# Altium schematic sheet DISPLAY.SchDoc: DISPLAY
size A4; CompanyName: Arduino srl; DrawnBy: Silvio Navaretti; DocumentNumber: ASX00039; SheetNumber: 4; SheetTotal: 8; RevAuthor: Silvio Navaretti
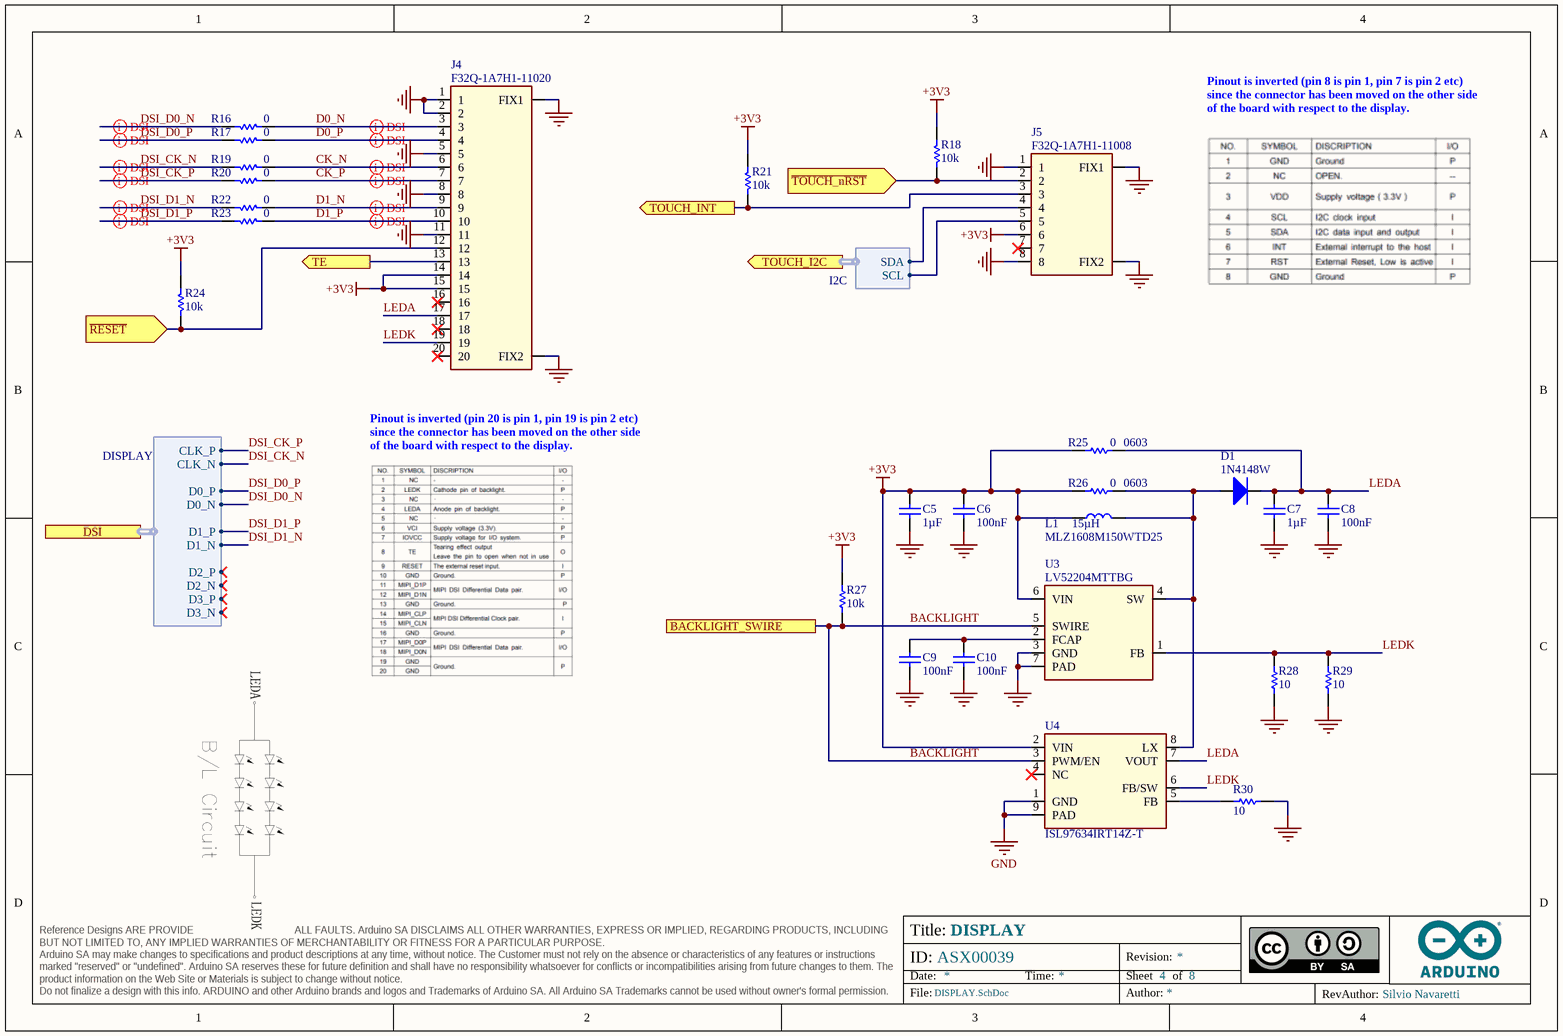
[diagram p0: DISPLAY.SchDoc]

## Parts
C5  value 1µF  [CAP-0603]  (hidden comment: TMK107BJ105MAHT)
C6  value 100nF  [CAP-0603]  (hidden comment: C0603C104K5RAC3190)
C7  value 1µF  [CAP-0603]  (hidden comment: TMK107BJ105MAHT)
C8  value 100nF  [CAP-0603]  (hidden comment: C0603C104K5RAC3190)
C9  value 100nF  [CAP-0603]  (hidden comment: C0603C104K5RAC3190)
C10  value 100nF  [CAP-0603]  (hidden comment: C0603C104K5RAC3190)
D1  1N4148W  [SOD123-1]
J4  F32Q-1A7H1-11020  [F32R-1A7H1-11020]
J5  F32Q-1A7H1-11008  [F32R-1A7H1-11008]
L1  MLZ1608M150WTD25  Inductance: 15µH  [L-0603]
R16  value 0  [RES-0603]  (hidden comment: CRCW06030000Z0EAC)
R17  value 0  [RES-0603]  (hidden comment: CRCW06030000Z0EAC)
R18  value 10k  [RES-0603]  (hidden comment: CRCW060310K0JNEAC)
R19  value 0  [RES-0603]  (hidden comment: CRCW06030000Z0EAC)
R20  value 0  [RES-0603]  (hidden comment: CRCW06030000Z0EAC)
R21  value 10k  [RES-0603]  (hidden comment: CRCW060310K0JNEAC)
R22  value 0  [RES-0603]  (hidden comment: CRCW06030000Z0EAC)
R23  value 0  [RES-0603]  (hidden comment: CRCW06030000Z0EAC)
R24  value 10k  [RES-0603]  (hidden comment: CRCW060310K0JNEAC)
R25  value 0  Case Code (Imperial): 0603  [RES-0603]  (hidden comment: CRCW06030000Z0EAC)
R26  value 0  Case Code (Imperial): 0603  [RES-0603]  (hidden comment: CRCW06030000Z0EAC)
R27  value 10k  [RES-0603]  (hidden comment: CRCW060310K0JNEAC)
R28  value 10  [RES-0603]  (hidden comment: CRCW060310R0FKEAC)
R29  value 10  [RES-0603]  (hidden comment: CRCW060310R0FKEAC)
R30  value 10  [RES-0603]  (hidden comment: CRCW060310R0FKEAC)
U3  LV52204MTTBG  [QFN65P200X200X80_HS-7L]
U4  ISL97634IRT14Z-T  [PQFN0P300X200X80_HS-9L]

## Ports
BACKLIGHT_SWIRE, DSI (harness DISPLAY), TE (out), TOUCH_I2C (out, harness I2C), TOUCH_INT (out), ~{RESET} (in), ~{TOUCH_nRST} (in)

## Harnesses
DISPLAY: CLK_N, CLK_P, D0_N, D0_P, D1_N, D1_P, D2_N, D2_P, D3_N, D3_P
I2C: SDA, SCL

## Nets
+3V3: C5.2 C6.2 J4.14 J4.15 J5.6 L1.1 R18.2 R21.2 R24.2 R25.1 R26.1 R27.2 U3.6(VIN) U4.2(VIN)
GND: C5.1 C6.1 C7.1 C8.1 C9.1 C10.1 J4.1 J4.2 J4.5 J4.8 J4.11 J4.FIX1 J4.FIX2 J5.1 J5.8 J5.FIX1 J5.FIX2 R28.1 R29.1 R30.1 U3.3(GND) U3.7(PAD) U4.1(GND) U4.9(PAD)
BACKLIGHT: R27.1 U3.5(SWIRE) U4.3(PWM/EN) ; port BACKLIGHT_SWIRE
CK_N: J4.6 R19.2
CK_P: J4.7 R20.2
D0_N: J4.3 R16.2
D0_P: J4.4 R17.2
D1_N: J4.9 R22.2
D1_P: J4.10 R23.2
DSI_CK_N: R19.1 ; port DSI.CLK_N
DSI_CK_P: R20.1 ; port DSI.CLK_P
DSI_D0_N: R16.1 ; port DSI.D0_N
DSI_D0_P: R17.1 ; port DSI.D0_P
DSI_D1_N: R22.1 ; port DSI.D1_N
DSI_D1_P: R23.1 ; port DSI.D1_P
LEDA: C7.2 C8.2 D1.C J4.17 R25.2 U4.7(VOUT)
LEDK: J4.19 R28.2 R29.2 U3.1(FB) U4.6(FB/SW)
~{RESET}: J4.12 R24.1 ; port ~{RESET}
~{TOUCH_nRST}: J5.2 R18.1 ; port ~{TOUCH_nRST}
TE: J4.13 ; port TE
TOUCH_INT: J5.3 R21.1 ; port TOUCH_INT
NetC9_2: C9.2 C10.2 U3.2(FCAP)
NetD1_A: D1.A L1.2 R26.2 U3.4(SW) U4.8(LX)
NetJ5_4: J5.4 ; port TOUCH_I2C.SDA
NetJ5_5: J5.5 ; port TOUCH_I2C.SCL
NetR30_2: R30.2 U4.5(FB)

Not connected (* = marked no-connect by the designer): J4 16* 18* 20*; J5 7*; U4 4(NC)*

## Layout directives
differential pair; differential pair class DSI: CK_N, CK_P, D0_N, D0_P, D1_N, D1_P, DSI_CK_N, DSI_CK_P, DSI_D0_N, DSI_D0_P, DSI_D1_N, DSI_D1_P

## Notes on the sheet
- Pinout is inverted (pin 8 is pin 1, pin 7 is pin 2 etc) since the connector has been moved on the other side of the board with respect to the display.
- Pinout is inverted (pin 20 is pin 1, pin 19 is pin 2 etc) since the connector has been moved on the other side of the board with respect to the display.

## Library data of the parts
C5 C7 = C0077-A.10: CAP CHIP 0603 1UF 25V X5R 20%; Manufacturer: Taiyo Yuden; Code Arduino: C0077
C6 C8-C10 = C0043-A.11: CAP CHIP 0603 100nF 50V X7R 10%; Manufacturer: KEMET; Code Arduino: 0015
D1 = D0029-A.4: DIODE FAST SMD 200mA 100V SOD123; Manufacturer: Vishay; Code Arduino: 0290; Device Type: Diode gen. Purp
J4 = J0161-A.2: CONN FFC SMD HORIZONTAL TOP CONNECTION 20POS 0.5mm; Manufacturer: Amphenol; Code Arduino: J0161
J5 = J0235-A.3: CONN FFC SMD HORIZONTAL TOP CONNECTION 8POS 0.5mm; Manufacturer: Amphenol; Code Arduino: J0235
L1 = I0064-A.2: IND SMD 15uH Isat 70mA Imax 200mA 2MHz 0603; Manufacturer: TDK; Code Arduino: I0064; Series Resistance: 1.5; Tolerance: 20%
R16 R17 R19 R20 R22 R23 R25 R26 = R0096-A.13: RES CHIP 0603 0R 1/10W; Manufacturer: Vishay; Power: 100mW; Tolerance: J; Code Arduino: 0233
R18 R21 R24 R27 = R0090-A.13: RES CHIP 0603 10k 5% 1/10W B.5k; Manufacturer: Vishay; Code Arduino: 0028; Power: 100mW
R28-R30 = R0188-A.11: RES CHIP 0603 10R 1% 1/10W; Manufacturer: Vishay; Package Width: 0.8mm; Rated Power Dissipation (P): 100mW; Code Arduino: R0188; Package Height: 0.45mm; Package Length: 1.6mm; Temperature Coefficient: -100100ppm/°C; Working Voltage: 75V
U3 = U0125-A.8: IC LED BOOST DRIVER PWM DIMMING VIN 2V7 TO 5V5 VOUT MAX 40V; Manufacturer: ON Semiconductor; Dimming: PWM,Single-Wire; Min Input Voltage: 2.7V; Max Input Voltage: 5.5V; Code Arduino: U0125; Min Output Voltage: 37V; Number of Channels: 1; Max Output Voltage: 39V; Nominal Input Voltage (DC): 3.6V; Output Current per Channel: 700mA; Frequency: 600kHz
U4 = U0264-A.5: IC WHITE LED DRIVER W/PW DIM 26V TDFN-EP-8; Manufacturer: Renesas; Code Arduino: U0264; Min Supply Voltage: 2.4V; Max Supply Voltage: 5.5V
